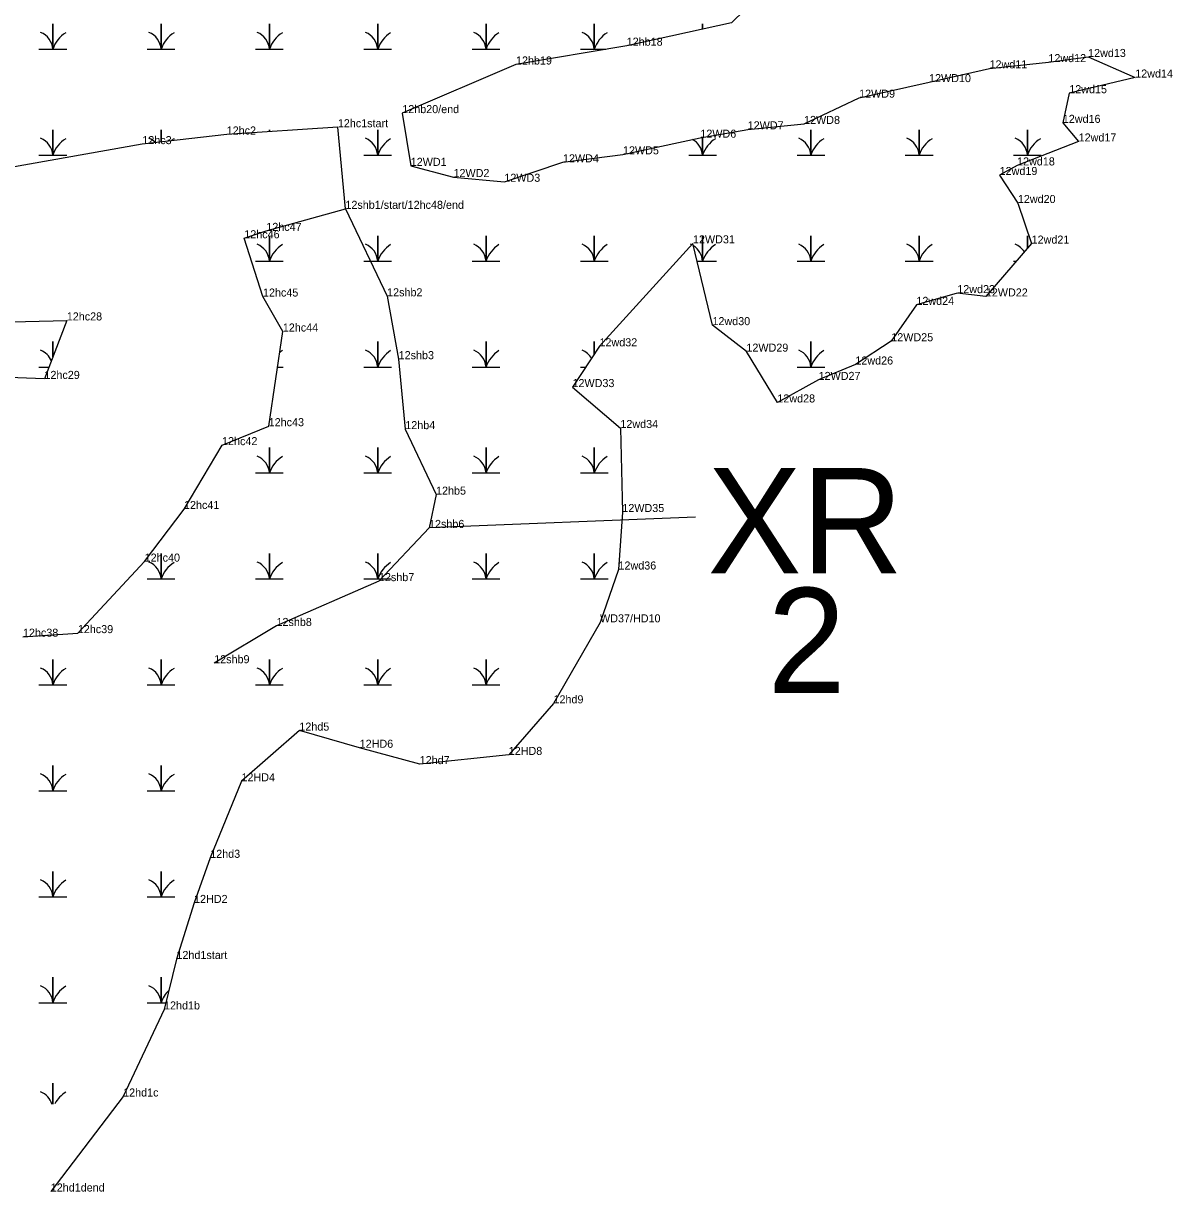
# Model space of a CAD drawing. Extents: x 2072529 to 2268796, y 436423 to 470397.
# Drawn here: x 2229910 to 2230624, y 450807 to 451533 of the extents above; entities that cross this region are included whole.
import ezdxf

# ---------------------------------------------------------------- set-up
doc = ezdxf.new("R2010")
doc.units = 0
for name, color, linetype in [('Default', 7, 'Continuous'), ('Exist Environmental Wetland Boundary', 7, 'Continuous'), ('Exist Environmental Wetland Boundary Cogo Comment', 7, 'Continuous'), ('Exist Environmental Wetland Boundary Cogo Point CELL', 7, 'Continuous'), ('Exist Hydro Jurisdictional Stream or Body of Water NEU Mitigable', 7, 'Continuous'), ('Exist Hydro Jurisdictional Stream or Body of Water NEU Mitigable Cogo Comment', 7, 'Continuous'), ('Exist Hydro Swamp or Marsh', 7, 'Continuous')]:
    doc.layers.add(name, color=color, linetype=linetype)

msp = doc.modelspace()

# ---------------------------------------------------------------- linework, layer by layer
at = {"layer": 'Default'}
msp.add_line((2230327.26, 451226.02), (2230161.74, 451219.34), dxfattribs=at)
at = {"layer": 'Exist Environmental Wetland Boundary'}
for points in [[(2229916.54, 452059.99), (2229931.73, 452045.2), (2229943.3, 452005.34), (2229953.58, 451984.88), (2229977.5, 451937.44), (2230012.98, 451931.99), (2230048.35, 451882.27), (2230063.46, 451838.07), (2230091.25, 451787.04), (2230121.85, 451731.65), (2230140.84, 451670.66), (2230175.01, 451631.24), (2230199.96, 451595.2), (2230260.4, 451582.17), (2230326.07, 451568.04), (2230374.56, 451557.62), (2230349.49, 451533.09), (2230284.51, 451518.88), (2230215.75, 451507.19), (2230145.13, 451476.98), (2230150.38, 451444.23)], [(2230150.38, 451444.23), (2230176.96, 451437.29), (2230208.52, 451434.35), (2230244.94, 451446.43), (2230282.2, 451451.39), (2230330.23, 451461.73), (2230359.63, 451466.92), (2230394.67, 451470.26), (2230428.85, 451486.57), (2230472.27, 451496.23), (2230509.83, 451504.79), (2230546.4, 451508.67), (2230571.05, 451511.85), (2230600.31, 451499.07), (2230559.34, 451489.36), (2230555.34, 451470.92), (2230565.16, 451459.38), (2230526.94, 451444.49), (2230516.1, 451438.56), (2230527.43, 451421.16), (2230535.97, 451395.95), (2230507.55, 451363.11), (2230489.79, 451365.18), (2230464.42, 451357.89), (2230448.81, 451335.3), (2230426.52, 451320.84), (2230403.68, 451311.27), (2230378.07, 451297.27), (2230358.84, 451328.84), (2230337.77, 451345.3), (2230325.67, 451396.1), (2230267.61, 451332.15), (2230250.85, 451306.82), (2230280.59, 451281.42), (2230281.8, 451229.23), (2230279.41, 451193.52), (2230267.97, 451160.7), (2230239.04, 451110.4), (2230211.25, 451078.36), (2230155.94, 451072.65), (2230118.67, 451082.81), (2230081.22, 451093.46), (2230045.28, 451061.97), (2230025.87, 451014.45), (2230015.82, 450986.42), (2230004.89, 450951.6)], [(2230109.82, 451417.54), (2230105.12, 451468.21), (2230036.1, 451463.7), (2229983.68, 451457.72), (2229891.22, 451441.44)], [(2229909.57, 451151.78), (2229943.66, 451154.01), (2229985.15, 451198.43), (2230009.59, 451231.1), (2230033.22, 451270.77), (2230062.17, 451282.53), (2230070.96, 451341.33), (2230058.64, 451363.06), (2230047.01, 451399.26), (2230060.7, 451403.83), (2230109.82, 451417.54)], [(2229885.27, 451347.01), (2229936.8, 451348.22), (2229922.92, 451311.91), (2229872.85, 451313.81)], [(2230004.89, 450951.6), (2229997.2, 450920.28), (2229971.8, 450866.21), (2229926.84, 450807.2)]]:
    msp.add_lwpolyline(points, dxfattribs=at)
at = {"layer": 'Exist Environmental Wetland Boundary Cogo Point CELL'}
for p, q in [((2230284.51, 451518.88), (2230284.51, 451518.88)), ((2230571.05, 451511.85), (2230571.05, 451511.85)), ((2230215.75, 451507.19), (2230215.75, 451507.19)), ((2230509.83, 451504.79), (2230509.83, 451504.79)), ((2230546.4, 451508.67), (2230546.4, 451508.67)), ((2230600.31, 451499.07), (2230600.31, 451499.07)), ((2230472.27, 451496.23), (2230472.27, 451496.23)), ((2230559.34, 451489.36), (2230559.34, 451489.36)), ((2230428.85, 451486.57), (2230428.85, 451486.57)), ((2230145.13, 451476.98), (2230145.13, 451476.98)), ((2230105.12, 451468.21), (2230105.12, 451468.21)), ((2230394.67, 451470.26), (2230394.67, 451470.26)), ((2230555.34, 451470.92), (2230555.34, 451470.92)), ((2230036.1, 451463.7), (2230036.1, 451463.7)), ((2230330.23, 451461.73), (2230330.23, 451461.73)), ((2230359.63, 451466.92), (2230359.63, 451466.92)), ((2229983.68, 451457.72), (2229983.68, 451457.72)), ((2230565.16, 451459.38), (2230565.16, 451459.38)), ((2230244.94, 451446.43), (2230244.94, 451446.43)), ((2230282.2, 451451.39), (2230282.2, 451451.39)), ((2230150.38, 451444.23), (2230150.38, 451444.23)), ((2230516.1, 451438.56), (2230516.1, 451438.56)), ((2230526.94, 451444.49), (2230526.94, 451444.49)), ((2230176.96, 451437.29), (2230176.96, 451437.29)), ((2230208.52, 451434.35), (2230208.52, 451434.35)), ((2230109.82, 451417.54), (2230109.82, 451417.54)), ((2230109.82, 451417.54), (2230109.82, 451417.54)), ((2230527.43, 451421.16), (2230527.43, 451421.16)), ((2230060.7, 451403.83), (2230060.7, 451403.83)), ((2230047.01, 451399.26), (2230047.01, 451399.26)), ((2230325.67, 451396.1), (2230325.67, 451396.1)), ((2230535.97, 451395.95), (2230535.97, 451395.95)), ((2230058.64, 451363.06), (2230058.64, 451363.06)), ((2230135.72, 451363.22), (2230135.72, 451363.22)), ((2230489.79, 451365.18), (2230489.79, 451365.18)), ((2230507.55, 451363.11), (2230507.55, 451363.11)), ((2230464.42, 451357.89), (2230464.42, 451357.89)), ((2229936.8, 451348.22), (2229936.8, 451348.22)), ((2230337.77, 451345.3), (2230337.77, 451345.3)), ((2230070.96, 451341.33), (2230070.96, 451341.33)), ((2230267.61, 451332.15), (2230267.61, 451332.15)), ((2230448.81, 451335.3), (2230448.81, 451335.3)), ((2230142.89, 451324.16), (2230142.89, 451324.16)), ((2230358.84, 451328.84), (2230358.84, 451328.84)), ((2230426.52, 451320.84), (2230426.52, 451320.84)), ((2229922.92, 451311.91), (2229922.92, 451311.91)), ((2230403.68, 451311.27), (2230403.68, 451311.27)), ((2230250.85, 451306.82), (2230250.85, 451306.82)), ((2230378.07, 451297.27), (2230378.07, 451297.27)), ((2230062.17, 451282.53), (2230062.17, 451282.53)), ((2230146.99, 451280.7), (2230146.99, 451280.7)), ((2230280.59, 451281.42), (2230280.59, 451281.42)), ((2230033.22, 451270.77), (2230033.22, 451270.77)), ((2230166.11, 451240.02), (2230166.11, 451240.02)), ((2230009.59, 451231.1), (2230009.59, 451231.1)), ((2230281.8, 451229.23), (2230281.8, 451229.23)), ((2230161.74, 451219.34), (2230161.74, 451219.34)), ((2229985.15, 451198.43), (2229985.15, 451198.43)), ((2230279.41, 451193.52), (2230279.41, 451193.52)), ((2230130.65, 451186.31), (2230130.65, 451186.31)), ((2230067.03, 451158.45), (2230067.03, 451158.45)), ((2230267.97, 451160.7), (2230267.97, 451160.7)), ((2229943.66, 451154.01), (2229943.66, 451154.01)), ((2230028.33, 451135.31), (2230028.33, 451135.31)), ((2230239.04, 451110.4), (2230239.04, 451110.4)), ((2230081.22, 451093.46), (2230081.22, 451093.46)), ((2230118.67, 451082.81), (2230118.67, 451082.81)), ((2230211.25, 451078.36), (2230211.25, 451078.36)), ((2230155.94, 451072.65), (2230155.94, 451072.65)), ((2230045.28, 451061.97), (2230045.28, 451061.97)), ((2230025.87, 451014.45), (2230025.87, 451014.45)), ((2230015.82, 450986.42), (2230015.82, 450986.42)), ((2230004.89, 450951.6), (2230004.89, 450951.6)), ((2229997.2, 450920.28), (2229997.2, 450920.28)), ((2229971.8, 450866.21), (2229971.8, 450866.21)), ((2229926.84, 450807.2), (2229926.84, 450807.2))]:
    msp.add_line(p, q, dxfattribs=at)
at = {"layer": 'Exist Hydro Jurisdictional Stream or Body of Water NEU Mitigable'}
msp.add_lwpolyline([(2230109.82, 451417.54), (2230135.72, 451363.22), (2230142.89, 451324.16), (2230146.99, 451280.7), (2230166.11, 451240.02), (2230161.74, 451219.34), (2230130.65, 451186.31), (2230067.03, 451158.45), (2230028.33, 451135.31)], dxfattribs=at)
at = {"layer": 'Exist Hydro Swamp or Marsh'}
for points in [[(2229919.53, 451516.68), (2229928.13, 451516.68), (2229928.13, 451532.46), (2229928.13, 451516.68), (2229936.73, 451516.68)], [(2229986.78, 451516.68), (2229995.38, 451516.68), (2229995.38, 451532.46), (2229995.38, 451516.68), (2230003.98, 451516.68)], [(2230054.03, 451516.68), (2230062.63, 451516.68), (2230062.63, 451532.46), (2230062.63, 451516.68), (2230071.23, 451516.68)], [(2230121.28, 451516.68), (2230129.88, 451516.68), (2230129.88, 451532.46), (2230129.88, 451516.68), (2230138.48, 451516.68)], [(2230188.53, 451516.68), (2230197.13, 451516.68), (2230197.13, 451532.46), (2230197.13, 451516.68), (2230205.73, 451516.68)], [(2230255.78, 451516.68), (2230264.38, 451516.68), (2230264.38, 451532.46), (2230264.38, 451516.68), (2230271.53, 451516.68)], [(2230331.63, 451529.19), (2230331.63, 451532.46), (2230331.63, 451529.19)], [(2229919.53, 451450.88), (2229928.13, 451450.88), (2229928.13, 451466.66), (2229928.13, 451450.88), (2229936.73, 451450.88)], [(2229995.38, 451459.06), (2229995.38, 451466.66), (2229995.38, 451459.06)], [(2230062.63, 451465.43), (2230062.63, 451466.66), (2230062.63, 451465.43)], [(2230121.28, 451450.88), (2230129.88, 451450.88), (2230129.88, 451466.66), (2230129.88, 451450.88), (2230138.48, 451450.88)], [(2230323.03, 451450.88), (2230331.63, 451450.88), (2230331.63, 451461.98)], [(2230331.63, 451461.98), (2230331.63, 451450.88), (2230340.23, 451450.88)], [(2230390.28, 451450.88), (2230398.88, 451450.88), (2230398.88, 451466.66), (2230398.88, 451450.88), (2230407.48, 451450.88)], [(2230457.53, 451450.88), (2230466.13, 451450.88), (2230466.13, 451466.66), (2230466.13, 451450.88), (2230474.73, 451450.88)], [(2230524.78, 451450.88), (2230533.38, 451450.88), (2230533.38, 451466.66), (2230533.38, 451450.88), (2230541.98, 451450.88)], [(2230054.03, 451385.08), (2230062.63, 451385.08), (2230062.63, 451400.86), (2230062.63, 451385.08), (2230071.23, 451385.08)], [(2230121.28, 451385.08), (2230129.88, 451385.08), (2230129.88, 451400.86), (2230129.88, 451385.08), (2230138.48, 451385.08)], [(2230188.53, 451385.08), (2230197.13, 451385.08), (2230197.13, 451400.86), (2230197.13, 451385.08), (2230205.73, 451385.08)], [(2230255.78, 451385.08), (2230264.38, 451385.08), (2230264.38, 451400.86), (2230264.38, 451385.08), (2230272.98, 451385.08)], [(2230328.3, 451385.08), (2230331.63, 451385.08), (2230331.63, 451400.86), (2230331.63, 451385.08), (2230340.23, 451385.08)], [(2230390.28, 451385.08), (2230398.88, 451385.08), (2230398.88, 451400.86), (2230398.88, 451385.08), (2230407.48, 451385.08)], [(2230457.53, 451385.08), (2230466.13, 451385.08), (2230466.13, 451400.86), (2230466.13, 451385.08), (2230474.73, 451385.08)], [(2230533.38, 451392.96), (2230533.38, 451400.86), (2230533.38, 451392.96)], [(2230524.78, 451385.08), (2230526.56, 451385.08)], [(2229928.13, 451325.54), (2229928.13, 451335.06), (2229928.13, 451325.54)], [(2230121.28, 451319.28), (2230129.88, 451319.28), (2230129.88, 451335.06), (2230129.88, 451319.28), (2230138.48, 451319.28)], [(2230188.53, 451319.28), (2230197.13, 451319.28), (2230197.13, 451335.06), (2230197.13, 451319.28), (2230205.73, 451319.28)], [(2230264.38, 451327.26), (2230264.38, 451335.06), (2230264.38, 451327.26)], [(2230390.28, 451319.28), (2230398.88, 451319.28), (2230398.88, 451335.06), (2230398.88, 451319.28), (2230407.48, 451319.28)], [(2229919.53, 451319.28), (2229925.74, 451319.28)], [(2230067.66, 451319.28), (2230071.23, 451319.28)], [(2230255.78, 451319.28), (2230259.09, 451319.28)], [(2230054.03, 451253.48), (2230062.63, 451253.48), (2230062.63, 451269.26), (2230062.63, 451253.48), (2230071.23, 451253.48)], [(2230121.28, 451253.48), (2230129.88, 451253.48), (2230129.88, 451269.26), (2230129.88, 451253.48), (2230138.48, 451253.48)], [(2230188.53, 451253.48), (2230197.13, 451253.48), (2230197.13, 451269.26), (2230197.13, 451253.48), (2230205.73, 451253.48)], [(2230255.78, 451253.48), (2230264.38, 451253.48), (2230264.38, 451269.26), (2230264.38, 451253.48), (2230272.98, 451253.48)], [(2229986.78, 451187.68), (2229995.38, 451187.68), (2229995.38, 451203.46), (2229995.38, 451187.68), (2230003.98, 451187.68)], [(2230054.03, 451187.68), (2230062.63, 451187.68), (2230062.63, 451203.46), (2230062.63, 451187.68), (2230071.23, 451187.68)], [(2230121.28, 451187.68), (2230129.88, 451187.68), (2230129.88, 451203.46), (2230129.88, 451187.68), (2230138.48, 451187.68)], [(2230188.53, 451187.68), (2230197.13, 451187.68), (2230197.13, 451203.46), (2230197.13, 451187.68), (2230205.73, 451187.68)], [(2230255.78, 451187.68), (2230264.38, 451187.68), (2230264.38, 451203.46), (2230264.38, 451187.68), (2230272.98, 451187.68)], [(2229919.53, 451121.88), (2229928.13, 451121.88), (2229928.13, 451137.66), (2229928.13, 451121.88), (2229936.73, 451121.88)], [(2229986.78, 451121.88), (2229995.38, 451121.88), (2229995.38, 451137.66), (2229995.38, 451121.88), (2230003.98, 451121.88)], [(2230054.03, 451121.88), (2230062.63, 451121.88), (2230062.63, 451137.66), (2230062.63, 451121.88), (2230071.23, 451121.88)], [(2230121.28, 451121.88), (2230129.88, 451121.88), (2230129.88, 451137.66), (2230129.88, 451121.88), (2230138.48, 451121.88)], [(2230188.53, 451121.88), (2230197.13, 451121.88), (2230197.13, 451137.66), (2230197.13, 451121.88), (2230205.73, 451121.88)], [(2229919.53, 451056.08), (2229928.13, 451056.08), (2229928.13, 451071.86), (2229928.13, 451056.08), (2229936.73, 451056.08)], [(2229986.78, 451056.08), (2229995.38, 451056.08), (2229995.38, 451071.86), (2229995.38, 451056.08), (2230003.98, 451056.08)], [(2229919.53, 450990.28), (2229928.13, 450990.28), (2229928.13, 451006.06), (2229928.13, 450990.28), (2229936.73, 450990.28)], [(2229986.78, 450990.28), (2229995.38, 450990.28), (2229995.38, 451006.06), (2229995.38, 450990.28), (2230003.98, 450990.28)], [(2229919.53, 450924.48), (2229928.13, 450924.48), (2229928.13, 450940.26), (2229928.13, 450924.48), (2229936.73, 450924.48)], [(2229986.78, 450924.48), (2229995.38, 450924.48), (2229995.38, 450940.26), (2229995.38, 450924.48), (2229998.23, 450924.48)], [(2229928.13, 450861.44), (2229928.13, 450874.46), (2229928.13, 450861.44)]]:
    msp.add_lwpolyline(points, dxfattribs=at)
for centre, radius, start, end in [((2229915.86, 451515.79), 12.3, 4.14034, 67.53497), ((2229946.37, 451510.62), 19.22, 122.12745, 161.62219), ((2229983.11, 451515.79), 12.3, 4.14034, 67.53497), ((2230013.62, 451510.62), 19.22, 122.12745, 161.62219), ((2230050.36, 451515.79), 12.3, 4.14034, 67.53497), ((2230080.87, 451510.62), 19.22, 122.12745, 161.62219), ((2230117.61, 451515.79), 12.3, 4.14034, 67.53497), ((2230148.12, 451510.62), 19.22, 122.12745, 161.62219), ((2230184.86, 451515.79), 12.3, 4.14034, 67.53497), ((2230215.37, 451510.62), 19.22, 122.12745, 161.62219), ((2230252.11, 451515.79), 12.3, 4.14034, 67.53497), ((2230282.62, 451510.62), 19.22, 122.12745, 161.62219), ((2229915.86, 451449.99), 12.3, 4.14034, 67.53497), ((2229946.37, 451444.82), 19.22, 122.12745, 161.62219), ((2229983.11, 451449.99), 12.3, 44.78858, 67.53497), ((2230013.62, 451444.82), 19.22, 122.12745, 128.99556), ((2230117.61, 451449.99), 12.3, 4.14034, 67.53497), ((2230148.12, 451444.82), 19.22, 122.12745, 161.62219), ((2230319.36, 451449.99), 12.3, 4.14034, 60.53572), ((2230349.87, 451444.82), 19.22, 122.12745, 161.62219), ((2230386.61, 451449.99), 12.3, 4.14034, 67.53497), ((2230417.12, 451444.82), 19.22, 122.12745, 161.62219), ((2230453.86, 451449.99), 12.3, 4.14034, 67.53497), ((2230484.37, 451444.82), 19.22, 122.12745, 161.62219), ((2230521.11, 451449.99), 12.3, 4.14034, 67.53497), ((2230551.62, 451444.82), 19.22, 122.12745, 161.62219), ((2230050.36, 451384.19), 12.3, 4.14034, 67.53497), ((2230080.87, 451379.02), 19.22, 122.12745, 161.62219), ((2230117.61, 451384.19), 12.3, 4.14034, 67.53497), ((2230148.12, 451379.02), 19.22, 122.12745, 161.62219), ((2230184.86, 451384.19), 12.3, 4.14034, 67.53497), ((2230215.37, 451379.02), 19.22, 122.12745, 161.62219), ((2230252.11, 451384.19), 12.3, 4.14034, 67.53497), ((2230282.62, 451379.02), 19.22, 122.12745, 161.62219), ((2230319.36, 451384.19), 12.3, 63.5033, 67.53497), ((2230349.87, 451379.02), 19.22, 122.12745, 161.62219), ((2230386.61, 451384.19), 12.3, 4.14034, 67.53497), ((2230417.12, 451379.02), 19.22, 122.12745, 161.62219), ((2230453.86, 451384.19), 12.3, 4.14034, 67.53497), ((2230484.37, 451379.02), 19.22, 122.12745, 161.62219), ((2230521.11, 451384.19), 12.3, 32.42377, 67.53497), ((2230319.36, 451384.19), 12.3, 4.14034, 57.03215), ((2229915.86, 451318.39), 12.3, 22.68844, 67.53497), ((2230080.87, 451313.22), 19.22, 122.12745, 128.06467), ((2230117.61, 451318.39), 12.3, 4.14034, 67.53497), ((2230148.12, 451313.22), 19.22, 122.12745, 161.62219), ((2230184.86, 451318.39), 12.3, 4.14034, 67.53497), ((2230215.37, 451313.22), 19.22, 122.12745, 161.62219), ((2230252.11, 451318.39), 12.3, 30.81207, 67.53497), ((2230386.61, 451318.39), 12.3, 4.14034, 67.53497), ((2230417.12, 451313.22), 19.22, 122.12745, 161.62219), ((2230050.36, 451252.59), 12.3, 4.14034, 67.53497), ((2230080.87, 451247.42), 19.22, 122.12745, 161.62219), ((2230117.61, 451252.59), 12.3, 4.14034, 67.53497), ((2230148.12, 451247.42), 19.22, 122.12745, 161.62219), ((2230184.86, 451252.59), 12.3, 4.14034, 67.53497), ((2230215.37, 451247.42), 19.22, 122.12745, 161.62219), ((2230252.11, 451252.59), 12.3, 4.14034, 67.53497), ((2230282.62, 451247.42), 19.22, 122.12745, 161.62219), ((2229983.11, 451186.79), 12.3, 4.14034, 67.53497), ((2230013.62, 451181.62), 19.22, 122.12745, 161.62219), ((2230050.36, 451186.79), 12.3, 4.14034, 67.53497), ((2230080.87, 451181.62), 19.22, 122.12745, 161.62219), ((2230117.61, 451186.79), 12.3, 4.14034, 67.53497), ((2230148.12, 451181.62), 19.22, 122.12745, 161.62219), ((2230184.86, 451186.79), 12.3, 4.14034, 67.53497), ((2230215.37, 451181.62), 19.22, 122.12745, 161.62219), ((2230252.11, 451186.79), 12.3, 4.14034, 67.53497), ((2230282.62, 451181.62), 19.22, 122.12745, 161.62219), ((2229915.86, 451120.99), 12.3, 4.14034, 67.53497), ((2229946.37, 451115.82), 19.22, 122.12745, 161.62219), ((2229983.11, 451120.99), 12.3, 4.14034, 67.53497), ((2230013.62, 451115.82), 19.22, 122.12745, 161.62219), ((2230050.36, 451120.99), 12.3, 4.14034, 67.53497), ((2230080.87, 451115.82), 19.22, 122.12745, 161.62219), ((2230117.61, 451120.99), 12.3, 4.14034, 67.53497), ((2230148.12, 451115.82), 19.22, 122.12745, 161.62219), ((2230184.86, 451120.99), 12.3, 4.14034, 67.53497), ((2230215.37, 451115.82), 19.22, 122.12745, 161.62219), ((2229915.86, 451055.19), 12.3, 4.14034, 67.53497), ((2229946.37, 451050.02), 19.22, 122.12745, 161.62219), ((2229983.11, 451055.19), 12.3, 4.14034, 67.53497), ((2230013.62, 451050.02), 19.22, 122.12745, 161.62219), ((2229915.86, 450989.39), 12.3, 4.14034, 67.53497), ((2229946.37, 450984.22), 19.22, 122.12745, 161.62219), ((2229983.11, 450989.39), 12.3, 4.14034, 67.53497), ((2230013.62, 450984.22), 19.22, 122.12745, 161.62219), ((2229915.86, 450923.59), 12.3, 4.14034, 67.53497), ((2229946.37, 450918.42), 19.22, 122.12745, 161.62219), ((2229983.11, 450923.59), 12.3, 4.14034, 67.53497), ((2230013.62, 450918.42), 19.22, 134.73349, 161.62219), ((2229915.86, 450857.79), 12.3, 16.74352, 67.53497), ((2229946.37, 450852.62), 19.22, 122.12745, 151.67727)]:
    msp.add_arc(centre, radius, start, end, dxfattribs=at)

# ---------------------------------------------------------------- texts
at = {"layer": 'Default'}
for s, p in [('XR', (2230334.75, 451191.2)), ('2', (2230371.93, 451116.74))]:
    msp.add_text(s, height=65.34, dxfattribs=at).set_placement(p)
at = {"layer": 'Exist Environmental Wetland Boundary Cogo Comment'}
for s, p in [('12hb18', (2230284.51, 451518.88)), ('12hb19', (2230215.75, 451507.19)), ('12wd12', (2230546.4, 451508.67)), ('12wd13', (2230571.05, 451511.85)), ('12wd11', (2230509.83, 451504.79)), ('12wd14', (2230600.31, 451499.07)), ('12WD10', (2230472.27, 451496.23)), ('12WD9', (2230428.85, 451486.57)), ('12wd15', (2230559.34, 451489.36)), ('12hb20/end', (2230145.13, 451476.98)), ('12WD8', (2230394.67, 451470.26)), ('12wd16', (2230555.34, 451470.92)), ('12hc2', (2230036.1, 451463.7)), ('12hc1start', (2230105.12, 451468.21)), ('12WD7', (2230359.63, 451466.92)), ('12hc3', (2229983.68, 451457.72)), ('12WD6', (2230330.23, 451461.73)), ('12wd17', (2230565.16, 451459.38)), ('12WD5', (2230282.2, 451451.39)), ('12WD1', (2230150.38, 451444.23)), ('12WD4', (2230244.94, 451446.43)), ('12wd18', (2230526.94, 451444.49)), ('12WD2', (2230176.96, 451437.29)), ('12WD3', (2230208.52, 451434.35)), ('12wd19', (2230516.1, 451438.56)), ('12wd20', (2230527.43, 451421.16)), ('12hc46', (2230047.01, 451399.26)), ('12hc47', (2230060.7, 451403.83)), ('12WD31', (2230325.67, 451396.1)), ('12wd21', (2230535.97, 451395.95)), ('12hc45', (2230058.64, 451363.06)), ('12wd23', (2230489.79, 451365.18)), ('12WD22', (2230507.55, 451363.11)), ('12wd24', (2230464.42, 451357.89)), ('12hc28', (2229936.8, 451348.22)), ('12hc44', (2230070.96, 451341.33)), ('12wd30', (2230337.77, 451345.3)), ('12wd32', (2230267.61, 451332.15)), ('12WD25', (2230448.81, 451335.3)), ('12WD29', (2230358.84, 451328.84)), ('12wd26', (2230426.52, 451320.84)), ('12hc29', (2229922.92, 451311.91)), ('12WD27', (2230403.68, 451311.27)), ('12WD33', (2230250.85, 451306.82)), ('12wd28', (2230378.07, 451297.27)), ('12hc43', (2230062.17, 451282.53)), ('12wd34', (2230280.59, 451281.42)), ('12hc42', (2230033.22, 451270.77)), ('12hc41', (2230009.59, 451231.1)), ('12WD35', (2230281.8, 451229.23)), ('12hc40', (2229985.15, 451198.43)), ('12wd36', (2230279.41, 451193.52)), ('WD37/HD10', (2230267.97, 451160.7)), ('12hc38', (2229909.57, 451151.78)), ('12hc39', (2229943.66, 451154.01)), ('12hd9', (2230239.04, 451110.4)), ('12hd5', (2230081.22, 451093.46)), ('12HD6', (2230118.67, 451082.81)), ('12HD8', (2230211.25, 451078.36)), ('12hd7', (2230155.94, 451072.65)), ('12HD4', (2230045.28, 451061.97)), ('12hd3', (2230025.87, 451014.45)), ('12HD2', (2230015.82, 450986.42)), ('12hd1start', (2230004.89, 450951.6)), ('12hd1b', (2229997.2, 450920.28)), ('12hd1c', (2229971.8, 450866.21)), ('12hd1dend', (2229926.84, 450807.2))]:
    msp.add_text(s, height=5, dxfattribs=at).set_placement(p)
at = {"layer": 'Exist Hydro Jurisdictional Stream or Body of Water NEU Mitigable Cogo Comment'}
for s, p in [('12shb1/start/12hc48/end', (2230109.82, 451417.54)), ('12shb2', (2230135.72, 451363.22)), ('12shb3', (2230142.89, 451324.16)), ('12hb4', (2230146.99, 451280.7)), ('12hb5', (2230166.11, 451240.02)), ('12shb6', (2230161.74, 451219.34)), ('12shb7', (2230130.65, 451186.31)), ('12shb8', (2230067.03, 451158.45)), ('12shb9', (2230028.33, 451135.31))]:
    msp.add_text(s, height=5, dxfattribs=at).set_placement(p)

doc.saveas('drawing.dxf')
